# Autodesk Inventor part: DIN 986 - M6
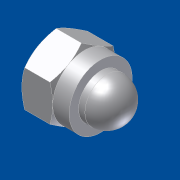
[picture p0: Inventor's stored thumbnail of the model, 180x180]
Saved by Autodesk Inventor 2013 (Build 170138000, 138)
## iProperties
Created: 2002-06
Part Number: DIN 986 - M6
Material: Standard
Catalog Web Link: file:///D:/Programme/Inventor%205.3/Content/Din/index.htm?doNavigateId=CDA42BAF-C454-11D4-A9F1-0080AD303E0A|5F329F67B0DC11D4BA6900C04F798F98|true
Description: Hutmutter
Document SubType Name: Standard Catalog Part
Standard: DIN 986 - M6
Designer: dl
Density: 1 g/cm^3
Control State: 0
Master: False
Checked Out: False
Shininess: 20.0
Length Units: 11269
Angle Units: 11279
Time Units: 11290
Mass Units: 11283
Length Display Precision: 3
Angle Display Precision: 2
Compacted: True
KLASSIFIKATION: 31161705
HERSTELLER: DIN Normsystem
Density: 0.0
Volumn: 0.0
Area: 0.0
PropertySet Name: Model Information
Author: dl
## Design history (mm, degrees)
feature "Basis1"
body "Solid1"
